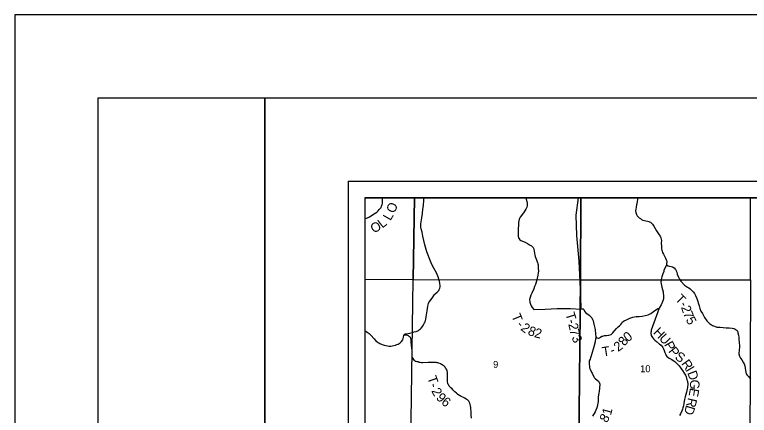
# Model space of a CAD drawing. Extents: x 0 to 34, y 0 to 22.
# Drawn here: x 0 to 4.406, y 19.595 to 22 of the extents above; entities that cross this region are included whole.
import ezdxf

# ---------------------------------------------------------------- set-up
doc = ezdxf.new("R2010")
doc.units = 0
for name, color, linetype in [('GM_X_Corporation', 7, 'Continuous'), ('GM_X_County_Road', 7, 'Continuous'), ('GM_X_Section_Text', 7, 'Continuous'), ('GM_X_Township_Road', 7, 'Continuous'), ('GM_X_Township_Road_Text', 7, 'Continuous'), ('GM_X_Township_Text', 7, 'Continuous'), ('SH_Border', 7, 'Continuous'), ('SH_Cut_Line', 7, 'Continuous'), ('SH_Data', 7, 'Continuous')]:
    doc.layers.add(name, color=color, linetype=linetype)

msp = doc.modelspace()

# ---------------------------------------------------------------- linework, layer by layer
at = {"layer": 'GM_X_Corporation'}
for points in [[(2.3972, 20.9), (2.1, 20.9), (2.1, 20.4122), (2.3901, 20.4092)], [(3.3964, 20.9), (2.3972, 20.9), (2.3901, 20.4092), (3.3928, 20.4074)], [(4.4126, 20.9), (3.3964, 20.9), (3.3928, 20.4074), (4.4129, 20.4084)], [(3.3928, 20.4074), (3.384, 19.4149), (2.3752, 19.4244), (2.3901, 20.4092)], [(3.3928, 20.4074), (4.4129, 20.4084), (4.4084, 19.4053), (3.384, 19.4149)]]:
    msp.add_lwpolyline(points, close=True, dxfattribs=at)
at = {"layer": 'GM_X_County_Road'}
msp.add_lwpolyline([(2.1, 20.1039), (2.1135, 20.0944), (2.1261, 20.0862), (2.1318, 20.0808), (2.1369, 20.0752), (2.1552, 20.0539), (2.1659, 20.0422), (2.1731, 20.036), (2.1791, 20.032), (2.1837, 20.0298), (2.1905, 20.0267), (2.2042, 20.0206), (2.2153, 20.0167), (2.2267, 20.0131), (2.2368, 20.0112), (2.2465, 20.0102), (2.2564, 20.0101), (2.2649, 20.011), (2.2738, 20.0131), (2.2839, 20.0167), (2.2911, 20.019), (2.2998, 20.0224), (2.3057, 20.0259), (2.3124, 20.0309), (2.3202, 20.0385), (2.3273, 20.0473), (2.3306, 20.055), (2.3325, 20.0632), (2.3346, 20.075), (2.3363, 20.0781), (2.3389, 20.0812), (2.3436, 20.0838), (2.3514, 20.0848), (2.36, 20.086), (2.3699, 20.0879), (2.3836, 20.0915), (2.3963, 20.0951), (2.4079, 20.0984), (2.4149, 20.1009), (2.421, 20.1039), (2.4288, 20.1094), (2.4331, 20.1135), (2.4387, 20.119), (2.445, 20.1278), (2.4537, 20.1417), (2.4581, 20.1492), (2.461, 20.1555), (2.4636, 20.1631), (2.4662, 20.1727), (2.4684, 20.1867), (2.4735, 20.2227), (2.4775, 20.2494), (2.4795, 20.2589), (2.4813, 20.2651), (2.4845, 20.2715), (2.4903, 20.2803), (2.4983, 20.2911), (2.5075, 20.3038), (2.5141, 20.3137), (2.5182, 20.3194), (2.5214, 20.3236), (2.5337, 20.3349), (2.54, 20.3408), (2.5433, 20.345), (2.5457, 20.3497), (2.5477, 20.3535), (2.5497, 20.3587), (2.551, 20.366), (2.5513, 20.3743), (2.55, 20.3857), (2.5472, 20.4004), (2.5441, 20.4129), (2.5397, 20.4259), (2.5342, 20.4393), (2.5289, 20.4498), (2.5209, 20.464), (2.5132, 20.4782), (2.5043, 20.4966), (2.4987, 20.5094), (2.4865, 20.54), (2.4804, 20.5553), (2.4724, 20.5756), (2.4674, 20.5893), (2.4597, 20.6176), (2.4535, 20.6442), (2.4486, 20.6705), (2.4437, 20.6936), (2.4385, 20.7141), (2.4367, 20.7225), (2.4352, 20.733), (2.4363, 20.7436), (2.4418, 20.7803), (2.4456, 20.8054), (2.4484, 20.8317), (2.4512, 20.8547), (2.4537, 20.8868), (2.454, 20.8973), (2.4542, 20.9)], dxfattribs=at)
at = {"layer": 'GM_X_Township_Road'}
for points in [[(2.1, 20.7732), (2.1037, 20.7755), (2.1156, 20.7813), (2.1278, 20.7869), (2.1378, 20.7923), (2.1408, 20.7939), (2.162, 20.8079), (2.1722, 20.8149), (2.1798, 20.8219), (2.1866, 20.8295), (2.1925, 20.8364), (2.1971, 20.8433), (2.2008, 20.8508), (2.2034, 20.8604), (2.2051, 20.8693), (2.2063, 20.8819), (2.2064, 20.889), (2.2061, 20.8953), (2.2068, 20.9)], [(3.0653, 20.9), (3.0673, 20.8933), (3.0713, 20.8784), (3.0736, 20.8688), (3.0742, 20.8583), (3.0736, 20.852), (3.072, 20.8453), (3.0699, 20.8396), (3.0662, 20.8323), (3.0516, 20.8106), (3.0323, 20.7835), (3.0266, 20.772), (3.0232, 20.762), (3.0215, 20.7529), (3.0211, 20.7413), (3.0203, 20.7113), (3.0205, 20.671), (3.0217, 20.6608), (3.0252, 20.6539), (3.03, 20.648), (3.0363, 20.6449), (3.0616, 20.6337), (3.0763, 20.626), (3.0885, 20.6185), (3.0997, 20.6114), (3.1053, 20.6067), (3.109, 20.6029), (3.111, 20.5986), (3.1147, 20.5818), (3.1173, 20.5661), (3.119, 20.5582), (3.1213, 20.5473), (3.1247, 20.539), (3.1355, 20.5124), (3.1379, 20.5037), (3.139, 20.4977), (3.1396, 20.4902), (3.1406, 20.4763), (3.1407, 20.4631), (3.1398, 20.4486), (3.1382, 20.4363), (3.1322, 20.4087), (3.1282, 20.395), (3.1232, 20.3809), (3.1185, 20.3673), (3.1138, 20.3547), (3.1007, 20.3278), (3.0962, 20.3159), (3.0913, 20.3027), (3.0885, 20.2897), (3.0891, 20.2739), (3.0928, 20.2617), (3.097, 20.2511), (3.1028, 20.2423), (3.1133, 20.2309), (3.1809, 20.2329), (3.2535, 20.2353), (3.3332, 20.2353), (3.3956, 20.2317)], [(3.3791, 20.9), (3.3662, 20.7971), (3.3691, 20.6737), (3.3831, 20.5209), (3.3883, 20.4385), (3.3931, 20.3057), (3.3956, 20.2317)], [(3.7371, 20.9), (3.7361, 20.8932), (3.7327, 20.8765), (3.7294, 20.8591), (3.7266, 20.8446), (3.7247, 20.8334), (3.7244, 20.8221), (3.7254, 20.8127), (3.7268, 20.806), (3.7288, 20.8), (3.7305, 20.7967), (3.7328, 20.793), (3.7356, 20.7896), (3.7397, 20.7857), (3.7456, 20.7807), (3.7525, 20.7756), (3.7593, 20.7712), (3.7674, 20.7673), (3.7766, 20.7644), (3.786, 20.7625), (3.7956, 20.7605), (3.8039, 20.7579), (3.8079, 20.7561), (3.8132, 20.7534), (3.8194, 20.7483), (3.8248, 20.7427), (3.8299, 20.7355), (3.8337, 20.73), (3.8412, 20.7164), (3.8488, 20.7029), (3.8533, 20.6961), (3.8651, 20.6787), (3.8707, 20.67), (3.8752, 20.661), (3.8778, 20.6526), (3.8788, 20.6442), (3.8782, 20.6275), (3.8792, 20.6108), (3.8796, 20.594), (3.8806, 20.5863), (3.8825, 20.5798), (3.8856, 20.5729), (3.8905, 20.5628), (3.9041, 20.538), (3.9089, 20.5244), (3.9108, 20.5162), (3.9112, 20.5119), (3.9103, 20.5055), (3.9085, 20.498), (3.9025, 20.4838), (3.8948, 20.4711), (3.894, 20.4644), (3.8926, 20.4587), (3.8871, 20.4448), (3.8812, 20.4266), (3.8776, 20.4096), (3.8767, 20.403), (3.8762, 20.3955), (3.8772, 20.384), (3.8788, 20.3742), (3.881, 20.3646), (3.8886, 20.3362), (3.8901, 20.3264), (3.8911, 20.3165), (3.8915, 20.3054), (3.8905, 20.2941), (3.8891, 20.2882), (3.8878, 20.2827), (3.8765, 20.2581), (3.8657, 20.2372), (3.8182, 20.1065), (3.8164, 20.0988), (3.8157, 20.0914), (3.8163, 20.0844), (3.8169, 20.0793), (3.8183, 20.0746), (3.8208, 20.0689), (3.8248, 20.062), (3.831, 20.0544), (3.8397, 20.0457), (3.849, 20.0377), (3.8678, 20.0227), (3.8765, 20.0153), (3.883, 20.0085), (3.8878, 20.0017), (3.8922, 19.9941), (3.896, 19.9839), (3.8995, 19.9723), (3.9026, 19.9638), (3.9047, 19.9586), (3.9073, 19.9541), (3.9121, 19.9483), (3.9178, 19.9435), (3.9249, 19.9388), (3.9407, 19.9304), (3.9499, 19.9245), (3.9587, 19.9178), (3.9668, 19.9104), (3.9759, 19.9016), (3.9848, 19.8912), (3.9997, 19.8718), (4.0054, 19.8635), (4.0153, 19.8487), (4.0233, 19.8349), (4.0274, 19.8249), (4.0297, 19.8175), (4.0322, 19.8081), (4.0349, 19.7996), (4.0361, 19.794), (4.0367, 19.7888), (4.0369, 19.7814), (4.0346, 19.7616), (4.0314, 19.7436), (4.0291, 19.7344), (4.0214, 19.7053), (4.0183, 19.6907), (4.0143, 19.6678), (4.0107, 19.6508), (4.0077, 19.6402), (4.0051, 19.6314), (4.0028, 19.6253), (4.0005, 19.6207), (3.9974, 19.6139), (3.9927, 19.6043), (3.9875, 19.5945)], [(3.9085, 20.498), (3.9201, 20.493), (3.9463, 20.4857), (3.9548, 20.4797), (3.9634, 20.4709), (3.9706, 20.4536), (3.9741, 20.4421), (3.9805, 20.4243), (3.9867, 20.4126), (3.9961, 20.3994), (4.0174, 20.3762), (4.0242, 20.3715), (4.0294, 20.3685), (4.0352, 20.3636), (4.0384, 20.3615), (4.0439, 20.3594), (4.0511, 20.3541), (4.057, 20.3491), (4.0633, 20.3426), (4.0699, 20.3352), (4.0763, 20.3264), (4.0837, 20.3141), (4.0912, 20.2952), (4.1043, 20.2516), (4.1087, 20.2365), (4.1156, 20.2205), (4.1245, 20.2051), (4.1377, 20.1811), (4.151, 20.1614), (4.1675, 20.1458), (4.1859, 20.1344), (4.1977, 20.1291), (4.2115, 20.1245), (4.2201, 20.1231), (4.2314, 20.1235), (4.2664, 20.1204), (4.285, 20.1197), (4.3031, 20.1177), (4.3122, 20.1157), (4.3213, 20.1121), (4.3274, 20.1077), (4.333, 20.1031), (4.3366, 20.0963), (4.3381, 20.0896), (4.3408, 20.0765), (4.3427, 20.0644), (4.3431, 20.0522), (4.3465, 20.0111), (4.3473, 20.0032), (4.3449, 19.9882), (4.3439, 19.9635), (4.3468, 19.9507), (4.3529, 19.9389), (4.362, 19.9274), (4.3716, 19.9095), (4.3744, 19.9042), (4.3787, 19.8915), (4.3832, 19.8634), (4.3879, 19.8431), (4.393, 19.8357), (4.401, 19.8278), (4.4141, 19.8117)], [(3.3956, 20.2317), (3.4028, 20.2338), (3.4086, 20.2338), (3.4134, 20.2305), (3.4177, 20.2197), (3.4235, 20.2123), (3.4325, 20.2056), (3.4452, 20.1965), (3.4622, 20.1791), (3.4662, 20.1708), (3.4695, 20.1627), (3.4741, 20.1412), (3.4807, 20.1096), (3.4837, 20.0827), (3.4847, 20.0662), (3.4891, 20.0608)], [(3.4891, 20.0608), (3.4931, 20.0593), (3.4992, 20.0574), (3.5025, 20.0579), (3.508, 20.0607), (3.5138, 20.0648), (3.5218, 20.0694), (3.5269, 20.0709), (3.5381, 20.0733), (3.5502, 20.0741), (3.5634, 20.0769), (3.5768, 20.0799), (3.5817, 20.0837), (3.5869, 20.0894), (3.5962, 20.1004), (3.6085, 20.116), (3.6192, 20.1252), (3.6267, 20.1314), (3.6347, 20.1399), (3.6407, 20.148), (3.6464, 20.1552), (3.6559, 20.1628), (3.6692, 20.169), (3.6894, 20.1781), (3.708, 20.1831), (3.7281, 20.1881), (3.7448, 20.1883), (3.7635, 20.1896), (3.7821, 20.1931), (3.7997, 20.198), (3.8146, 20.2068), (3.8321, 20.2184), (3.8568, 20.2351), (3.8605, 20.2365), (3.8657, 20.2372)], [(2.4224, 19.9143), (2.4195, 19.9151), (2.4132, 19.916), (2.4087, 19.917), (2.4049, 19.9185), (2.4009, 19.921), (2.3971, 19.9248), (2.3934, 19.9293), (2.3899, 19.9354), (2.3867, 19.9416), (2.3847, 19.9493), (2.3833, 19.9602), (2.3832, 19.9768), (2.3835, 19.9858), (2.3816, 20.0004), (2.3803, 20.0144), (2.3784, 20.0407), (2.3779, 20.0493), (2.3763, 20.0563), (2.3744, 20.061), (2.3705, 20.0652), (2.3665, 20.0685), (2.3618, 20.0717), (2.3577, 20.0738), (2.3497, 20.0757), (2.3423, 20.0758), (2.3346, 20.075)], [(3.4891, 20.0608), (3.4845, 20.0557), (3.481, 20.0354), (3.4744, 20.0069), (3.4688, 19.9913), (3.4628, 19.9726), (3.4579, 19.9525), (3.4561, 19.9467), (3.4542, 19.9408), (3.4506, 19.9325), (3.4461, 19.922), (3.4454, 19.9029), (3.447, 19.8878), (3.448, 19.8798), (3.4496, 19.875), (3.451, 19.8723), (3.458, 19.858), (3.4592, 19.853), (3.4631, 19.8479), (3.4734, 19.8268), (3.4761, 19.8215), (3.4811, 19.815), (3.4934, 19.8053), (3.5011, 19.7997), (3.5042, 19.7964), (3.5059, 19.7933), (3.5076, 19.7887), (3.5086, 19.7825), (3.5089, 19.7767), (3.5081, 19.7662), (3.5073, 19.7571), (3.5053, 19.7401), (3.5034, 19.7277), (3.4993, 19.7052), (3.4987, 19.7004), (3.4986, 19.6957), (3.4992, 19.6879), (3.4992, 19.6781), (3.4989, 19.6739), (3.4983, 19.6689), (3.4954, 19.6531), (3.4916, 19.64), (3.4859, 19.6259), (3.4807, 19.6154), (3.466, 19.5892)], [(2.74, 19.5778), (2.7372, 19.5959), (2.737, 19.6206), (2.7365, 19.6317), (2.7359, 19.6411), (2.7346, 19.6524), (2.7323, 19.66), (2.729, 19.6678), (2.7258, 19.6754), (2.7232, 19.6805), (2.7202, 19.6841), (2.7157, 19.6879), (2.7082, 19.6925), (2.7007, 19.697), (2.688, 19.7032), (2.6788, 19.7076), (2.6712, 19.712), (2.6645, 19.7162), (2.6568, 19.7215), (2.6489, 19.7276), (2.6402, 19.7358), (2.6287, 19.7469), (2.6231, 19.754), (2.6163, 19.7599), (2.6113, 19.7646), (2.6066, 19.7698), (2.603, 19.7751), (2.6003, 19.78), (2.5981, 19.7864), (2.5967, 19.7986), (2.5961, 19.8062), (2.5959, 19.8208), (2.5956, 19.8527), (2.5941, 19.8614), (2.591, 19.8683), (2.5877, 19.8743), (2.5843, 19.8787), (2.581, 19.8829), (2.5761, 19.8889), (2.5695, 19.8948), (2.5645, 19.8983), (2.5602, 19.9005), (2.5544, 19.903), (2.5444, 19.907), (2.5377, 19.9092), (2.533, 19.9105), (2.5287, 19.9111), (2.5202, 19.9119), (2.5097, 19.9119), (2.4913, 19.9116), (2.479, 19.9115), (2.4475, 19.9103), (2.4397, 19.9105), (2.4325, 19.9112), (2.4286, 19.9121), (2.4253, 19.9134), (2.4224, 19.9143)]]:
    msp.add_lwpolyline(points, dxfattribs=at)
at = {"layer": 'GM_X_Township_Text'}
msp.add_lwpolyline([(6.4525, 17.3965), (6.4653, 18.1777), (6.4655, 18.1862), (6.4767, 18.8745), (6.4767, 18.8755), (6.4827, 20.9), (2.1, 20.9), (2.1, 19.4241)], dxfattribs=at)
at = {"layer": 'SH_Border'}
for points in [[(0.5, 21.5), (1.5, 21.5), (1.5, 0.5), (0.5, 0.5)], [(1.5, 21.5), (33.5, 21.5), (33.5, 0.5), (1.5, 0.5)]]:
    msp.add_lwpolyline(points, close=True, dxfattribs=at)
at = {"layer": 'SH_Cut_Line'}
msp.add_lwpolyline([(0, 0), (34, 0), (34, 22), (0, 22)], close=True, dxfattribs=at)
at = {"layer": 'SH_Data'}
for p, q in [((2, 21), (9, 21)), ((2, 21), (2, 14)), ((2.1, 20.9), (2.1, 14.1)), ((2.1, 20.9), (8.9, 20.9))]:
    msp.add_line(p, q, dxfattribs=at)

# ---------------------------------------------------------------- texts
at = {"layer": 'GM_X_Section_Text'}
for s, height, p in [('9', 0.0419, (2.8695, 19.8794)), ('10', 0.04186, (3.7512, 19.8536))]:
    msp.add_text(s, height=height, rotation=0, dxfattribs=at).set_placement(p)
at = {"layer": 'GM_X_Township_Road_Text'}
for s, rotation, p in [('O', 68.0961, (2.2784, 20.804)), ('L', 60.1092, (2.2535, 20.7594)), ('O', 29.7471, (2.1535, 20.6855)), ('L', 37.9571, (2.2043, 20.7153)), ('T', 314.9485, (3.9581, 20.2888)), ('-', 297.6055, (3.9855, 20.2624)), ('2', 288.6785, (3.9954, 20.2438)), ('7', 291.5766, (4.0076, 20.2077)), ('T', 292.3601, (2.9784, 20.1919)), ('T', 286.7772, (3.3019, 20.204)), ('5', 297.7572, (4.0233, 20.1691)), ('-', 312.8616, (3.0065, 20.1341)), ('2', 322.9202, (3.0304, 20.1097)), ('2', 282.644, (3.32, 20.1418)), ('-', 285.4071, (3.314, 20.1636)), ('8', 338.6116, (3.0731, 20.0803)), ('2', 345.4553, (3.1127, 20.0653)), ('7', 281.9937, (3.3277, 20.1078)), ('0', 38.4136, (3.6775, 20.0323)), ('H', 314.2375, (3.8264, 20.0891)), ('3', 293.18, (3.3386, 20.0621)), ('8', 52.6308, (3.6589, 20.0072)), ('U', 313.4389, (3.8611, 20.0534)), ('T', 9.0459, (3.5278, 19.9473)), ('2', 37.2426, (3.6193, 19.9743)), ('P', 299.1414, (3.8933, 20.0202)), ('P', 308.1364, (3.9174, 19.9786)), ('-', 21.0139, (3.5822, 19.9574)), ('S', 326.3499, (3.9554, 19.9351)), ('R', 305.6411, (3.9952, 19.9046)), ('I', 301.2864, (4.0217, 19.8676)), ('T', 289.469, (2.4732, 19.8208)), ('D', 290.947, (4.0327, 19.8501)), ('-', 279.8371, (2.4867, 19.7832)), ('G', 271.5447, (4.0495, 19.8084)), ('2', 298.4795, (2.4973, 19.7412)), ('E', 259.4188, (4.0511, 19.7615)), ('9', 313.9436, (2.5238, 19.697)), ('6', 321.8, (2.5544, 19.6661)), ('R', 256.1105, (4.0394, 19.7036)), ('D', 253.5157, (4.0284, 19.659)), ('1', 74.7389, (3.5756, 19.5916)), ('8', 58.84, (3.5508, 19.5459))]:
    msp.add_text(s, height=0.0568, rotation=rotation, dxfattribs=at).set_placement(p)

doc.saveas('drawing.dxf')
